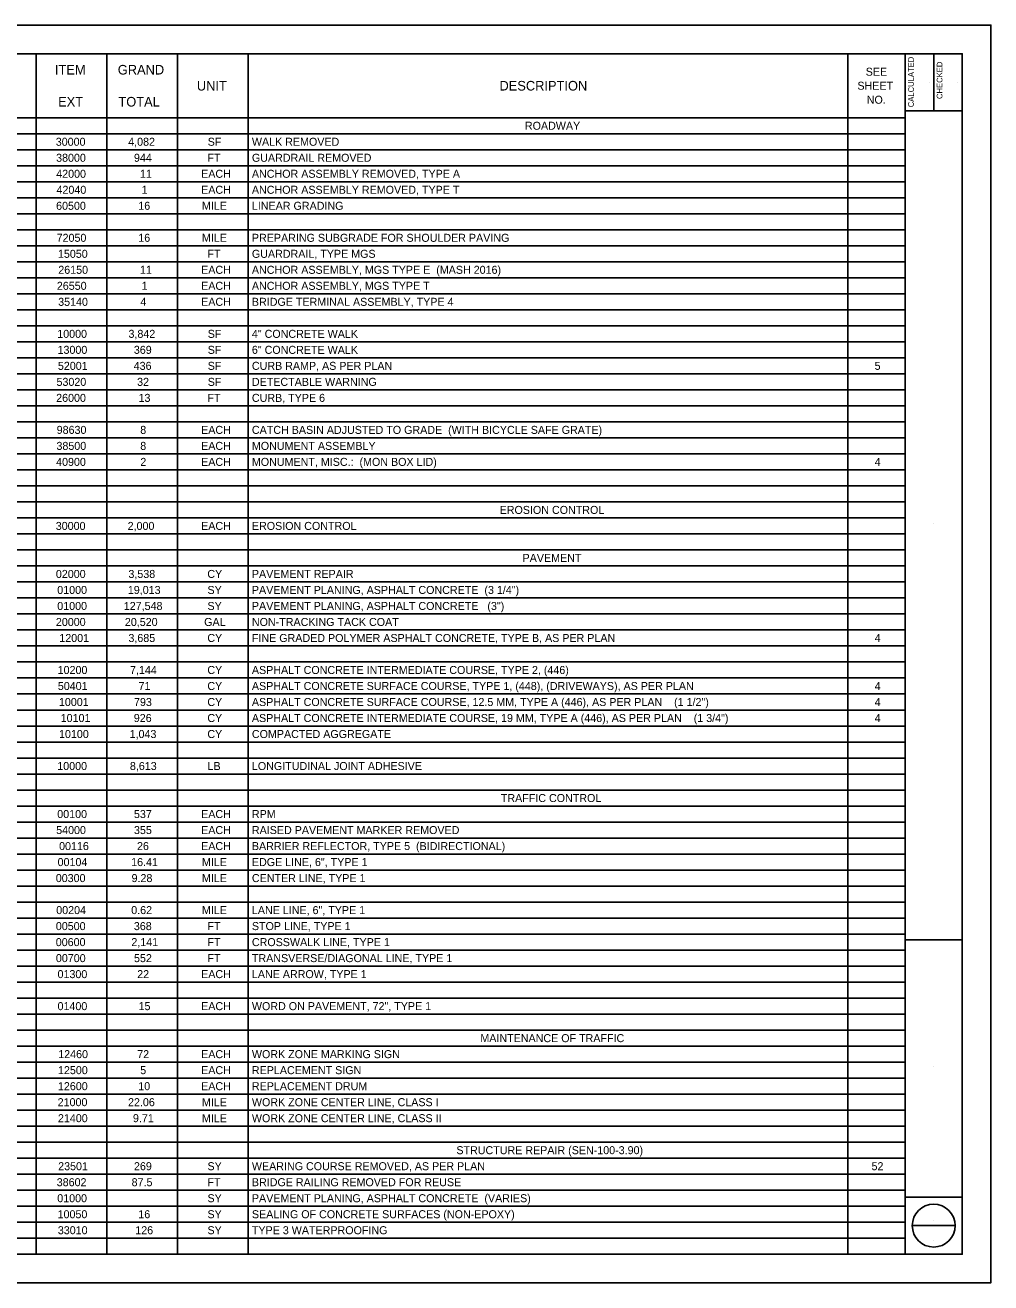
# Model space of a CAD drawing. Extents: x 43.3 to 77.3, y 1.1 to 23.1.
# Drawn here: x 60.38 to 77.28, y 1.13 to 23.13 of the extents above; entities that cross this region are included whole.
import ezdxf

# ---------------------------------------------------------------- set-up
doc = ezdxf.new("R2010")
doc.units = 0
for name, color, linetype in [('SH_Border', 7, 'Continuous'), ('SH_Cut_Line', 7, 'Continuous'), ('SH_Data', 7, 'Continuous'), ('SH_Text', 7, 'Continuous')]:
    doc.layers.add(name, color=color, linetype=linetype)

msp = doc.modelspace()

# ---------------------------------------------------------------- linework, layer by layer
at = {"layer": 'SH_Border'}
for p, q in [((75.775, 1.635), (75.775, 22.635)), ((76.275, 22.635), (76.275, 21.635)), ((75.775, 21.635), (76.775, 21.635)), ((75.775, 7.135), (76.775, 7.135)), ((75.775, 2.635), (76.775, 2.635))]:
    msp.add_line(p, q, dxfattribs=at)
msp.add_lwpolyline([(45.275, 22.635), (76.775, 22.635), (76.775, 1.635), (45.275, 1.635)], close=True, dxfattribs=at)
at = {"layer": 'SH_Cut_Line'}
msp.add_lwpolyline([(43.275, 1.135), (77.275, 1.135), (77.275, 23.135), (43.275, 23.135)], close=True, dxfattribs=at)
at = {"layer": 'SH_Data'}
for p, q in [((45.275, 22.635), (75.779, 22.635)), ((60.576, 22.635), (60.576, 1.635)), ((61.812, 22.635), (61.812, 1.635)), ((63.047, 22.635), (63.047, 1.635)), ((64.282, 22.635), (64.282, 1.635)), ((74.774, 22.635), (74.774, 1.635)), ((75.779, 22.635), (75.779, 1.635)), ((76.195, 22.138), (76.195, 22.138)), ((76.695, 22.138), (76.695, 22.138)), ((45.275, 21.515), (75.779, 21.515)), ((45.275, 21.235), (75.779, 21.235)), ((45.275, 20.955), (75.779, 20.955)), ((45.275, 20.675), (75.779, 20.675)), ((45.275, 20.395), (75.779, 20.395)), ((45.275, 20.115), (75.779, 20.115)), ((45.275, 19.835), (75.779, 19.835)), ((45.275, 19.555), (75.779, 19.555)), ((45.275, 19.275), (75.779, 19.275)), ((45.275, 18.995), (75.779, 18.995)), ((45.275, 18.715), (75.779, 18.715)), ((45.275, 18.435), (75.779, 18.435)), ((45.275, 18.155), (75.779, 18.155)), ((45.275, 17.875), (75.779, 17.875)), ((45.275, 17.595), (75.779, 17.595)), ((45.275, 17.315), (75.779, 17.315)), ((45.275, 17.035), (75.779, 17.035)), ((45.275, 16.755), (75.779, 16.755)), ((45.275, 16.475), (75.779, 16.475)), ((45.275, 16.195), (75.779, 16.195)), ((45.275, 15.915), (75.779, 15.915)), ((45.275, 15.635), (75.779, 15.635)), ((45.275, 15.355), (75.779, 15.355)), ((45.275, 15.075), (75.779, 15.075)), ((45.275, 14.795), (75.779, 14.795)), ((45.275, 14.515), (75.779, 14.515)), ((76.275, 14.426), (76.275, 14.426)), ((45.275, 14.235), (75.779, 14.235)), ((45.275, 13.955), (75.779, 13.955)), ((45.275, 13.675), (75.779, 13.675)), ((45.275, 13.395), (75.779, 13.395)), ((45.275, 13.115), (75.779, 13.115)), ((45.275, 12.835), (75.779, 12.835)), ((45.275, 12.555), (75.779, 12.555)), ((45.275, 12.275), (75.779, 12.275)), ((45.275, 11.995), (75.779, 11.995)), ((45.275, 11.715), (75.779, 11.715)), ((45.275, 11.435), (75.779, 11.435)), ((45.275, 11.155), (75.779, 11.155)), ((45.275, 10.875), (75.779, 10.875)), ((45.275, 10.595), (75.779, 10.595)), ((45.275, 10.315), (75.779, 10.315)), ((45.275, 10.035), (75.779, 10.035)), ((45.275, 9.755), (75.779, 9.755)), ((45.275, 9.475), (75.779, 9.475)), ((45.275, 9.195), (75.779, 9.195)), ((45.275, 8.915), (75.779, 8.915)), ((45.275, 8.635), (75.779, 8.635)), ((45.275, 8.355), (75.779, 8.355)), ((45.275, 8.075), (75.779, 8.075)), ((45.275, 7.795), (75.779, 7.795)), ((45.275, 7.515), (75.779, 7.515)), ((45.275, 7.235), (75.779, 7.235)), ((45.275, 6.955), (75.779, 6.955)), ((45.275, 6.675), (75.779, 6.675)), ((45.275, 6.395), (75.779, 6.395)), ((45.275, 6.115), (75.779, 6.115)), ((45.275, 5.835), (75.779, 5.835)), ((45.275, 5.555), (75.779, 5.555)), ((45.275, 5.275), (75.779, 5.275)), ((45.275, 4.995), (75.779, 4.995)), ((76.275, 4.926), (76.275, 4.926)), ((45.275, 4.715), (75.779, 4.715)), ((45.275, 4.435), (75.779, 4.435)), ((45.275, 4.155), (75.779, 4.155)), ((45.275, 3.875), (75.779, 3.875)), ((45.275, 3.595), (75.779, 3.595)), ((45.275, 3.315), (75.779, 3.315)), ((45.275, 3.035), (75.779, 3.035)), ((45.275, 2.755), (75.779, 2.755)), ((45.275, 2.475), (75.779, 2.475)), ((76.275, 2.22), (76.275, 2.22)), ((45.275, 2.195), (75.779, 2.195)), ((75.9, 2.135), (76.65, 2.135)), ((45.275, 1.915), (75.779, 1.915)), ((76.275, 1.88), (76.275, 1.88)), ((45.275, 1.635), (75.779, 1.635))]:
    msp.add_line(p, q, dxfattribs=at)
msp.add_circle((76.275, 2.135), 0.375, dxfattribs=at)

# ---------------------------------------------------------------- texts
for s, p in [('CALCULATED', (75.928, 21.699)), ('CHECKED', (76.428, 21.843))]:
    msp.add_text(s, height=0.1, rotation=90, dxfattribs=at).set_placement(p)
at = {"layer": 'SH_Text'}
for s, height, p in [('GRAND', 0.168, (62.002, 22.271)), ('ITEM', 0.168, (60.903, 22.271)), ('SEE', 0.14, (75.086, 22.25)), ('UNIT', 0.168, (63.385, 21.991)), ('DESCRIPTION', 0.168, (68.679, 21.991)), ('SHEET', 0.14, (74.941, 22.005)), ('EXT', 0.168, (60.958, 21.711)), ('TOTAL', 0.168, (62.013, 21.711)), ('NO.', 0.14, (75.104, 21.76)), ('ROADWAY', 0.14, (69.124, 21.305)), ('30000', 0.14, (60.917, 21.025)), ('4,082', 0.14, (62.184, 21.025)), ('SF', 0.14, (63.575, 21.025)), ('WALK REMOVED', 0.14, (64.348, 21.025)), ('38000', 0.14, (60.923, 20.745)), ('944', 0.14, (62.285, 20.745)), ('FT', 0.14, (63.571, 20.745)), ('GUARDRAIL REMOVED', 0.14, (64.348, 20.745)), ('42000', 0.14, (60.925, 20.465)), ('11', 0.14, (62.389, 20.465)), ('EACH', 0.14, (63.46, 20.465)), ('ANCHOR ASSEMBLY REMOVED, TYPE A', 0.14, (64.348, 20.465)), ('42040', 0.14, (60.93, 20.185)), ('1', 0.14, (62.419, 20.185)), ('EACH', 0.14, (63.46, 20.185)), ('ANCHOR ASSEMBLY REMOVED, TYPE T', 0.14, (64.348, 20.185)), ('60500', 0.14, (60.923, 19.905)), ('16', 0.14, (62.361, 19.905)), ('MILE', 0.14, (63.474, 19.905)), ('LINEAR GRADING', 0.14, (64.348, 19.905)), ('72050', 0.14, (60.932, 19.345)), ('16', 0.14, (62.361, 19.345)), ('MILE', 0.14, (63.474, 19.345)), ('PREPARING SUBGRADE FOR SHOULDER PAVING', 0.14, (64.348, 19.345)), ('15050', 0.14, (60.955, 19.065)), ('FT', 0.14, (63.571, 19.065)), ('GUARDRAIL, TYPE MGS', 0.14, (64.348, 19.065)), ('26150', 0.14, (60.961, 18.785)), ('11', 0.14, (62.389, 18.785)), ('EACH', 0.14, (63.46, 18.785)), ('ANCHOR ASSEMBLY, MGS TYPE E  (MASH 2016)', 0.14, (64.348, 18.785)), ('26550', 0.14, (60.936, 18.505)), ('1', 0.14, (62.419, 18.505)), ('EACH', 0.14, (63.46, 18.505)), ('ANCHOR ASSEMBLY, MGS TYPE T', 0.14, (64.348, 18.505)), ('35140', 0.14, (60.959, 18.225)), ('4', 0.14, (62.396, 18.225)), ('EACH', 0.14, (63.46, 18.225)), ('BRIDGE TERMINAL ASSEMBLY, TYPE 4', 0.14, (64.348, 18.225)), ('10000', 0.14, (60.943, 17.665)), ('3,842', 0.14, (62.189, 17.665)), ('SF', 0.14, (63.575, 17.665)), ('4" CONCRETE WALK', 0.14, (64.348, 17.665)), ('13000', 0.14, (60.948, 17.385)), ('369', 0.14, (62.283, 17.385)), ('SF', 0.14, (63.575, 17.385)), ('6" CONCRETE WALK', 0.14, (64.348, 17.385)), ('52001', 0.14, (60.954, 17.105)), ('436', 0.14, (62.28, 17.105)), ('SF', 0.14, (63.575, 17.105)), ('CURB RAMP, AS PER PLAN', 0.14, (64.348, 17.105)), ('5', 0.14, (75.242, 17.105)), ('53020', 0.14, (60.93, 16.825)), ('32', 0.14, (62.34, 16.825)), ('SF', 0.14, (63.575, 16.825)), ('DETECTABLE WARNING', 0.14, (64.348, 16.825)), ('26000', 0.14, (60.924, 16.545)), ('13', 0.14, (62.365, 16.545)), ('FT', 0.14, (63.571, 16.545)), ('CURB, TYPE 6', 0.14, (64.348, 16.545)), ('98630', 0.14, (60.933, 15.985)), ('8', 0.14, (62.395, 15.985)), ('EACH', 0.14, (63.46, 15.985)), ('CATCH BASIN ADJUSTED TO GRADE  (WITH BICYCLE SAFE GRATE)', 0.14, (64.348, 15.985)), ('38500', 0.14, (60.929, 15.705)), ('8', 0.14, (62.395, 15.705)), ('EACH', 0.14, (63.46, 15.705)), ('MONUMENT ASSEMBLY', 0.14, (64.348, 15.705)), ('40900', 0.14, (60.923, 15.425)), ('2', 0.14, (62.396, 15.425)), ('EACH', 0.14, (63.46, 15.425)), ('MONUMENT, MISC.:  (MON BOX LID)', 0.14, (64.348, 15.425)), ('4', 0.14, (75.243, 15.425)), ('EROSION CONTROL', 0.14, (68.682, 14.585)), ('30000', 0.14, (60.917, 14.305)), ('2,000', 0.14, (62.174, 14.305)), ('EACH', 0.14, (63.46, 14.305)), ('EROSION CONTROL', 0.14, (64.348, 14.305)), ('PAVEMENT', 0.14, (69.083, 13.745)), ('02000', 0.14, (60.919, 13.465)), ('3,538', 0.14, (62.188, 13.465)), ('CY', 0.14, (63.569, 13.465)), ('PAVEMENT REPAIR', 0.14, (64.348, 13.465)), ('01000', 0.14, (60.943, 13.185)), ('19,013', 0.14, (62.178, 13.185)), ('SY', 0.14, (63.571, 13.185)), ('PAVEMENT PLANING, ASPHALT CONCRETE  (3 1/4") ', 0.14, (64.348, 13.185)), ('01000', 0.14, (60.943, 12.905)), ('127,548', 0.14, (62.107, 12.905)), ('SY', 0.14, (63.571, 12.905)), ('PAVEMENT PLANING, ASPHALT CONCRETE   (3")', 0.14, (64.348, 12.905)), ('20000', 0.14, (60.919, 12.625)), ('20,520', 0.14, (62.126, 12.625)), ('GAL', 0.14, (63.513, 12.625)), ('NON-TRACKING TACK COAT', 0.14, (64.348, 12.625)), ('12001', 0.14, (60.979, 12.345)), ('3,685', 0.14, (62.188, 12.345)), ('CY', 0.14, (63.569, 12.345)), ('FINE GRADED POLYMER ASPHALT CONCRETE, TYPE B, AS PER PLAN', 0.14, (64.348, 12.345)), ('4', 0.14, (75.243, 12.345)), ('10200', 0.14, (60.95, 11.785)), ('7,144', 0.14, (62.216, 11.785)), ('CY', 0.14, (63.569, 11.785)), ('ASPHALT CONCRETE INTERMEDIATE COURSE, TYPE 2, (446)', 0.14, (64.348, 11.785)), ('50401', 0.14, (60.953, 11.505)), ('71', 0.14, (62.365, 11.505)), ('CY', 0.14, (63.569, 11.505)), ('ASPHALT CONCRETE SURFACE COURSE, TYPE 1, (448), (DRIVEWAYS), AS PER PLAN', 0.14, (64.348, 11.505)), ('4', 0.14, (75.243, 11.505)), ('10001', 0.14, (60.972, 11.225)), ('793', 0.14, (62.286, 11.225)), ('CY', 0.14, (63.569, 11.225)), ('ASPHALT CONCRETE SURFACE COURSE, 12.5 MM, TYPE A (446), AS PER PLAN    (1 1/2")', 0.14, (64.348, 11.225)), ('4', 0.14, (75.243, 11.225)), ('10101', 0.14, (61.003, 10.945)), ('926', 0.14, (62.282, 10.945)), ('CY', 0.14, (63.569, 10.945)), ('ASPHALT CONCRETE INTERMEDIATE COURSE, 19 MM, TYPE A (446), AS PER PLAN    (1 3/4")', 0.14, (64.348, 10.945)), ('4', 0.14, (75.243, 10.945)), ('10100', 0.14, (60.974, 10.665)), ('1,043', 0.14, (62.209, 10.665)), ('CY', 0.14, (63.569, 10.665)), ('COMPACTED AGGREGATE', 0.14, (64.348, 10.665)), ('10000', 0.14, (60.943, 10.105)), ('8,613', 0.14, (62.214, 10.105)), ('LB', 0.14, (63.572, 10.105)), ('LONGITUDINAL JOINT ADHESIVE', 0.14, (64.348, 10.105)), ('TRAFFIC CONTROL', 0.14, (68.703, 9.545)), ('00100', 0.14, (60.943, 9.265)), ('537', 0.14, (62.285, 9.265)), ('EACH', 0.14, (63.46, 9.265)), ('RPM', 0.14, (64.348, 9.265)), ('54000', 0.14, (60.924, 8.985)), ('355', 0.14, (62.285, 8.985)), ('EACH', 0.14, (63.46, 8.985)), ('RAISED PAVEMENT MARKER REMOVED', 0.14, (64.348, 8.985)), ('00116', 0.14, (60.975, 8.705)), ('26', 0.14, (62.338, 8.705)), ('EACH', 0.14, (63.46, 8.705)), ('BARRIER REFLECTOR, TYPE 5  (BIDIRECTIONAL)', 0.14, (64.348, 8.705)), ('00104', 0.14, (60.949, 8.425)), ('16.41', 0.14, (62.236, 8.425)), ('MILE', 0.14, (63.474, 8.425)), ('EDGE LINE, 6", TYPE 1', 0.14, (64.348, 8.425)), ('00300', 0.14, (60.917, 8.145)), ('9.28', 0.14, (62.243, 8.145)), ('MILE', 0.14, (63.474, 8.145)), ('CENTER LINE, TYPE 1', 0.14, (64.348, 8.145)), ('00204', 0.14, (60.925, 7.585)), ('0.62', 0.14, (62.237, 7.585)), ('MILE', 0.14, (63.474, 7.585)), ('LANE LINE, 6", TYPE 1', 0.14, (64.348, 7.585)), ('00500', 0.14, (60.918, 7.305)), ('368', 0.14, (62.283, 7.305)), ('FT', 0.14, (63.571, 7.305)), ('STOP LINE, TYPE 1', 0.14, (64.348, 7.305)), ('00600', 0.14, (60.917, 7.025)), ('2,141', 0.14, (62.239, 7.025)), ('FT', 0.14, (63.571, 7.025)), ('CROSSWALK LINE, TYPE 1', 0.14, (64.348, 7.025)), ('00700', 0.14, (60.919, 6.745)), ('552', 0.14, (62.286, 6.745)), ('FT', 0.14, (63.571, 6.745)), ('TRANSVERSE/DIAGONAL LINE, TYPE 1', 0.14, (64.348, 6.745)), ('01300', 0.14, (60.948, 6.465)), ('22', 0.14, (62.342, 6.465)), ('EACH', 0.14, (63.46, 6.465)), ('LANE ARROW, TYPE 1', 0.14, (64.348, 6.465)), ('01400', 0.14, (60.948, 5.905)), ('15', 0.14, (62.365, 5.905)), ('EACH', 0.14, (63.46, 5.905)), ('WORD ON PAVEMENT, 72", TYPE 1', 0.14, (64.348, 5.905)), ('MAINTENANCE OF TRAFFIC', 0.14, (68.345, 5.345)), ('12460', 0.14, (60.96, 5.065)), ('72', 0.14, (62.342, 5.065)), ('EACH', 0.14, (63.46, 5.065)), ('WORK ZONE MARKING SIGN', 0.14, (64.348, 5.065)), ('12500', 0.14, (60.956, 4.785)), ('5', 0.14, (62.395, 4.785)), ('EACH', 0.14, (63.46, 4.785)), ('REPLACEMENT SIGN', 0.14, (64.348, 4.785)), ('12600', 0.14, (60.955, 4.505)), ('10', 0.14, (62.36, 4.505)), ('EACH', 0.14, (63.46, 4.505)), ('REPLACEMENT DRUM', 0.14, (64.348, 4.505)), ('21000', 0.14, (60.95, 4.225)), ('22.06', 0.14, (62.181, 4.225)), ('MILE', 0.14, (63.474, 4.225)), ('WORK ZONE CENTER LINE, CLASS I', 0.14, (64.348, 4.225)), ('21400', 0.14, (60.955, 3.945)), ('9.71', 0.14, (62.267, 3.945)), ('MILE', 0.14, (63.474, 3.945)), ('WORK ZONE CENTER LINE, CLASS II', 0.14, (64.348, 3.945)), ('STRUCTURE REPAIR (SEN-100-3.90)', 0.14, (67.925, 3.385)), ('23501', 0.14, (60.959, 3.105)), ('269', 0.14, (62.285, 3.105)), ('SY', 0.14, (63.571, 3.105)), ('WEARING COURSE REMOVED, AS PER PLAN', 0.14, (64.348, 3.105)), ('52', 0.14, (75.188, 3.105)), ('38602', 0.14, (60.934, 2.825)), ('87.5', 0.14, (62.244, 2.825)), ('FT', 0.14, (63.571, 2.825)), ('BRIDGE RAILING REMOVED FOR REUSE', 0.14, (64.348, 2.825)), ('01000', 0.14, (60.943, 2.545)), ('SY', 0.14, (63.571, 2.545)), ('PAVEMENT PLANING, ASPHALT CONCRETE  (VARIES)', 0.14, (64.348, 2.545)), ('10050', 0.14, (60.949, 2.265)), ('16', 0.14, (62.361, 2.265)), ('SY', 0.14, (63.571, 2.265)), ('SEALING OF CONCRETE SURFACES (NON-EPOXY)', 0.14, (64.348, 2.265)), ('33010', 0.14, (60.953, 1.985)), ('126', 0.14, (62.308, 1.985)), ('SY', 0.14, (63.571, 1.985)), ('TYPE 3 WATERPROOFING', 0.14, (64.348, 1.985))]:
    msp.add_text(s, height=height, dxfattribs=at).set_placement(p)

doc.saveas('drawing.dxf')
